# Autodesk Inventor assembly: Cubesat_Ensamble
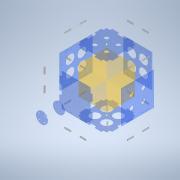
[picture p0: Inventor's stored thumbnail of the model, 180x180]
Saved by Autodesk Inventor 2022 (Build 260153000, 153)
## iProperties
Created: 2022-05
Part Number: Cubesat_Ensamble
Document SubType Name: Assembly
Designer: valen
Author: valen
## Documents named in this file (11)
- C:\Users\valen\Desktop\Estandar CubeSat - Programa AVES-20220531T050024Z-001\Estandar CubeSat - Programa AVES\3D - MODELS\IPT(Autodesk Inventor)\Cubesat_Ensamble_explosionado.iam
- C:\Users\valen\Desktop\Estandar CubeSat - Programa AVES-20220531T050024Z-001\Estandar CubeSat - Programa AVES\3D - MODELS\IPT(Autodesk Inventor)\Volumen interno .ipt
- C:\Users\valen\Desktop\Estandar CubeSat - Programa AVES-20220531T050024Z-001\Estandar CubeSat - Programa AVES\3D - MODELS\IPT(Autodesk Inventor)\1.Frontal.ipt
- C:\Users\valen\Desktop\Estandar CubeSat - Programa AVES-20220531T050024Z-001\Estandar CubeSat - Programa AVES\3D - MODELS\IPT(Autodesk Inventor)\3.Posterior.ipt
- C:\Users\valen\Desktop\Estandar CubeSat - Programa AVES-20220531T050024Z-001\Estandar CubeSat - Programa AVES\3D - MODELS\IPT(Autodesk Inventor)\2.Lateral derecha .ipt
- C:\Users\valen\Desktop\Estandar CubeSat - Programa AVES-20220531T050024Z-001\Estandar CubeSat - Programa AVES\3D - MODELS\IPT(Autodesk Inventor)\4.Lateral izquierda.ipt
- C:\Users\valen\Desktop\Estandar CubeSat - Programa AVES-20220531T050024Z-001\Estandar CubeSat - Programa AVES\3D - MODELS\IPT(Autodesk Inventor)\6.Inferior.ipt
- C:\Users\valen\Desktop\Estandar CubeSat - Programa AVES-20220531T050024Z-001\Estandar CubeSat - Programa AVES\3D - MODELS\IPT(Autodesk Inventor)\5.Superior.ipt
- C:\Users\valen\Desktop\Estandar CubeSat - Programa AVES-20220531T050024Z-001\Estandar CubeSat - Programa AVES\3D - MODELS\IPT(Autodesk Inventor)\7. Arandela.ipt
- C:\Users\valen\Desktop\Estandar CubeSat - Programa AVES-20220531T050024Z-001\Estandar CubeSat - Programa AVES\3D - MODELS\IPT(Autodesk Inventor)\8. Soporte tuercas.ipt
- C:\Users\valen\Desktop\Estandar CubeSat - Programa AVES-20220531T050024Z-001\Estandar CubeSat - Programa AVES\3D - MODELS\IPT(Autodesk Inventor)\Oring.ipt
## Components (29 placed, 10 different names)
1. Volumen interno :1 — Flush:1, Mate:1, Flush:2, Flush:3, Flush:4, Mate:2, Flush:5, Mate:3, Mate:4, Mate:5, Mate:6, Mate:7, Flush:7, Flush:8, Mate:8, Flush:9
2. 1.Frontal:1 — Flush:1, Mate:1, Flush:3, Flush:10, Mate:16, Mate:18, Mate:20, Mate:22, Mate:24
3. 3.Posterior:1 — Flush:4, Mate:2, Flush:5, Mate:26, Mate:28, Mate:30, Mate:32, Mate:34, Mate:36
4. 2.Lateral derecha :1 — Mate:3, Mate:4, Mate:5, Flush:6, Mate:23, Flush:14, Mate:25, Flush:15, Mate:27, Flush:16, Mate:29, Flush:17, Mate:39, Flush:22, Mate:41, Flush:23, Mate:47, Flush:26, Mate:49, Flush:27
5. 4.Lateral izquierda:1 — Mate:6, Mate:7, Flush:6, Mate:17, Flush:11, Mate:35, Flush:20, Mate:37, Flush:21, Mate:43, Flush:24, Mate:45, Flush:25, Mate:51, Flush:28, Mate:53, Flush:29
6. 6.Inferior:1 — Flush:7, Flush:8, Mate:8, Mate:11, Mate:12, Mate:13, Mate:19, Flush:12, Mate:21, Flush:13, Mate:31, Flush:18, Mate:33, Flush:19, Mate:46, Mate:48, Mate:50, Mate:52
7. 5.Superior:1 — Flush:9, Mate:38, Mate:40, Mate:42, Mate:44
8. 7. Arandela:1 — Mate:11, Mate:12, Mate:13, Mate:14, Mate:15
9. 8. Soporte tuercas:1 — Mate:14, Mate:15
10. Oring:1 — Flush:10
11. Oring:2 — Mate:16, Mate:17, Flush:11
12. Oring:3 — Mate:18, Mate:19, Flush:12
13. Oring:4 — Mate:20, Mate:21, Flush:13
14. Oring:5 — Mate:22, Mate:23, Flush:14
15. Oring:6 — Mate:24, Mate:25, Flush:15
16. Oring:7 — Mate:26, Mate:27, Flush:16
17. Oring:8 — Mate:36, Mate:37, Flush:21
18. Oring:9 — Mate:32, Mate:33, Flush:19
19. Oring:10 — Mate:34, Mate:35, Flush:20
20. Oring:11 — Mate:30, Mate:31, Flush:18
21. Oring:12 — Mate:28, Mate:29, Flush:17
22. Oring:13 — Mate:40, Mate:41, Flush:23
23. Oring:14 — Mate:42, Mate:43, Flush:24
24. Oring:15 — Mate:38, Mate:39, Flush:22
25. Oring:16 — Mate:44, Mate:45, Flush:25
26. Oring:17 — Mate:48, Mate:49, Flush:27
27. Oring:18 — Mate:46, Mate:47, Flush:26
28. Oring:19 — Mate:52, Mate:53, Flush:29
29. Oring:20 — Mate:50, Mate:51, Flush:28
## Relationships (80: Mate 51, Flush 29)
- Flush:1: Volumen interno :1 ↔ 1.Frontal:1
- Mate:1: Volumen interno :1 ↔ 1.Frontal:1
- Flush:2: Volumen interno :1
- Flush:3: Volumen interno :1 ↔ 1.Frontal:1
- Flush:4: Volumen interno :1 ↔ 3.Posterior:1
- Mate:2: Volumen interno :1 ↔ 3.Posterior:1
- Flush:5: Volumen interno :1 ↔ 3.Posterior:1
- Mate:3: Volumen interno :1 ↔ 2.Lateral derecha :1
- Mate:4: Volumen interno :1 ↔ 2.Lateral derecha :1
- Mate:5: Volumen interno :1 ↔ 2.Lateral derecha :1
- Mate:6: Volumen interno :1 ↔ 4.Lateral izquierda:1
- Mate:7: Volumen interno :1 ↔ 4.Lateral izquierda:1
- Flush:6: 2.Lateral derecha :1 ↔ 4.Lateral izquierda:1
- Flush:7: Volumen interno :1 ↔ 6.Inferior:1
- Flush:8: Volumen interno :1 ↔ 6.Inferior:1
- Mate:8: Volumen interno :1 ↔ 6.Inferior:1
- Flush:9: Volumen interno :1 ↔ 5.Superior:1
- Mate:11: 6.Inferior:1 ↔ 7. Arandela:1
- Mate:12: 6.Inferior:1 ↔ 7. Arandela:1
- Mate:13: 6.Inferior:1 ↔ 7. Arandela:1
- Mate:14: 7. Arandela:1 ↔ 8. Soporte tuercas:1
- Mate:15: 7. Arandela:1 ↔ 8. Soporte tuercas:1
- Flush:10: 1.Frontal:1 ↔ Oring:1
- Mate:16: 1.Frontal:1 ↔ Oring:2
- Mate:17: 4.Lateral izquierda:1 ↔ Oring:2
- Flush:11: 4.Lateral izquierda:1 ↔ Oring:2
- Mate:18: 1.Frontal:1 ↔ Oring:3
- Mate:19: 6.Inferior:1 ↔ Oring:3
- Flush:12: 6.Inferior:1 ↔ Oring:3
- Mate:20: 1.Frontal:1 ↔ Oring:4
- Mate:21: 6.Inferior:1 ↔ Oring:4
- Flush:13: 6.Inferior:1 ↔ Oring:4
- Mate:22: 1.Frontal:1 ↔ Oring:5
- Mate:23: 2.Lateral derecha :1 ↔ Oring:5
- Flush:14: 2.Lateral derecha :1 ↔ Oring:5
- Mate:24: 1.Frontal:1 ↔ Oring:6
- Mate:25: 2.Lateral derecha :1 ↔ Oring:6
- Flush:15: 2.Lateral derecha :1 ↔ Oring:6
- Mate:26: 3.Posterior:1 ↔ Oring:7
- Mate:27: 2.Lateral derecha :1 ↔ Oring:7
- Flush:16: 2.Lateral derecha :1 ↔ Oring:7
- Mate:28: 3.Posterior:1 ↔ Oring:12
- Mate:29: 2.Lateral derecha :1 ↔ Oring:12
- Flush:17: 2.Lateral derecha :1 ↔ Oring:12
- Mate:30: 3.Posterior:1 ↔ Oring:11
- Mate:31: 6.Inferior:1 ↔ Oring:11
- Flush:18: 6.Inferior:1 ↔ Oring:11
- Mate:32: 3.Posterior:1 ↔ Oring:9
- Mate:33: 6.Inferior:1 ↔ Oring:9
- Flush:19: 6.Inferior:1 ↔ Oring:9
- Mate:34: 3.Posterior:1 ↔ Oring:10
- Mate:35: 4.Lateral izquierda:1 ↔ Oring:10
- Flush:20: 4.Lateral izquierda:1 ↔ Oring:10
- Mate:36: 3.Posterior:1 ↔ Oring:8
- Mate:37: 4.Lateral izquierda:1 ↔ Oring:8
- Flush:21: 4.Lateral izquierda:1 ↔ Oring:8
- Mate:38: 5.Superior:1 ↔ Oring:15
- Mate:39: 2.Lateral derecha :1 ↔ Oring:15
- Flush:22: 2.Lateral derecha :1 ↔ Oring:15
- Mate:40: 5.Superior:1 ↔ Oring:13
- Mate:41: 2.Lateral derecha :1 ↔ Oring:13
- Flush:23: 2.Lateral derecha :1 ↔ Oring:13
- Mate:42: 5.Superior:1 ↔ Oring:14
- Mate:43: 4.Lateral izquierda:1 ↔ Oring:14
- Flush:24: 4.Lateral izquierda:1 ↔ Oring:14
- Mate:44: 5.Superior:1 ↔ Oring:16
- Mate:45: 4.Lateral izquierda:1 ↔ Oring:16
- Flush:25: 4.Lateral izquierda:1 ↔ Oring:16
- Mate:46: 6.Inferior:1 ↔ Oring:18
- Mate:47: 2.Lateral derecha :1 ↔ Oring:18
- Flush:26: 2.Lateral derecha :1 ↔ Oring:18
- Mate:48: 6.Inferior:1 ↔ Oring:17
- Mate:49: 2.Lateral derecha :1 ↔ Oring:17
- Flush:27: 2.Lateral derecha :1 ↔ Oring:17
- Mate:50: 6.Inferior:1 ↔ Oring:20
- Mate:51: 4.Lateral izquierda:1 ↔ Oring:20
- Flush:28: 4.Lateral izquierda:1 ↔ Oring:20
- Mate:52: 6.Inferior:1 ↔ Oring:19
- Mate:53: 4.Lateral izquierda:1 ↔ Oring:19
- Flush:29: 4.Lateral izquierda:1 ↔ Oring:19
